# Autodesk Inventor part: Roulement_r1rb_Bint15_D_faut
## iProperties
Created: 2011-10
Part Number: Roulement_r1rb_Bint15_D_faut
Document SubType Name: Modeling
Designer: Bruno
Author: Bruno
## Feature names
1. Base1
